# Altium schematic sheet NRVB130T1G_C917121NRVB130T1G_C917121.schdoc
size 127 x 101 mm
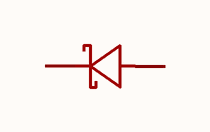
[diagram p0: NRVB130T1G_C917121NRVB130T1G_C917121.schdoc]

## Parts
U?  nrvb130t1g_c917121  [SOD-123_L2.7-W1.6-LS3.7-RD-1]  (value not drawn)

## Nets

Not connected (* = marked no-connect by the designer): U? 1(K) 2(A)

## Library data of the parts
U? = nrvb130t1g_c917121: 二极管配置:独立式;正向压降(Vf):350mV@100mA;直流反向耐压(Vr):30V;整流电流:1A;; Manufacturer: JSMSEMI(杰盛微); AddInBom: yes; ModelId: 528459655f7d4601a76356f3191c812b; ModelTransform: 151.575,66.929,0,0,0,0,0,0,0; Diode Configuration: 独立式; Voltage - DC Reverse(Vr): 30V; Current - Rectified: 1A; Reverse Leakage Current (Ir): 60uA@10V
